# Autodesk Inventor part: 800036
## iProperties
Created: 2007-10
Part Number: 800036
Document SubType Name: Modeling
Designer: AL
Density: 8.47 g/cm^3
Mass: 2.09349 g
Surface Area: 7.3166 cm^2
Volume: 0.247165 cm^3
Material: Brass, Soft Yellow
Description: BUSHING 4 MM THICK
Component Category: Fasteners
Author: AL
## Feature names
1. Revolution1
2. Extrusion2
